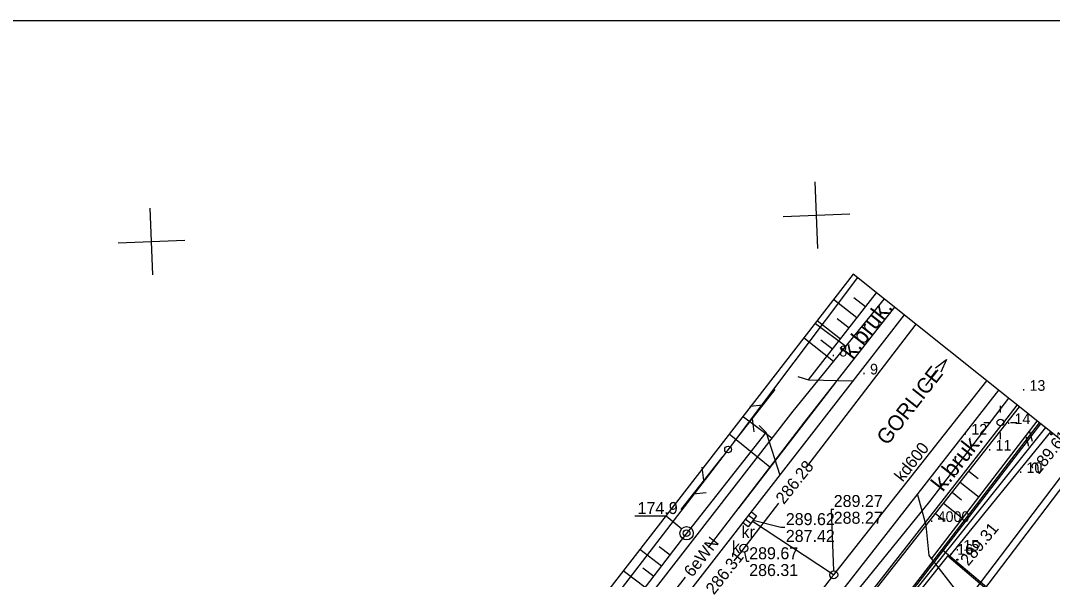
# Model space of a CAD drawing. Extents: x 4632591 to 4651936, y 5351032 to 5369988.
# Drawn here: x 4642040 to 4642117.6, y 5358443.5 to 5358485.5 of the extents above; entities that cross this region are included whole.
import ezdxf

# ---------------------------------------------------------------- set-up
doc = ezdxf.new("R2010")
doc.units = 0
for name, color, linetype in [('EBTOO_992', 7, 'Continuous'), ('EBUPP_312', 7, 'Continuous'), ('EDZPD_219', 7, 'Continuous'), ('EDZPX_299', 7, 'Continuous'), ('SDRPK_422', 7, 'Continuous'), ('SDRPK_423', 7, 'Continuous'), ('SDRPK_432', 7, 'Continuous'), ('SDRPZ_402', 7, 'Continuous'), ('SZOPO_902', 7, 'Continuous'), ('UEEPA_510', 7, 'Continuous'), ('UEEPB_665', 7, 'Continuous'), ('UEEPO_585', 7, 'Continuous'), ('UEETA_515', 7, 'Continuous'), ('UGGPO_583', 7, 'Continuous'), ('UKKPA_506', 7, 'Continuous'), ('UKKPA_509', 7, 'Continuous'), ('UKKPO_582', 7, 'Continuous'), ('UTTPA_510', 7, 'Continuous'), ('UTTPO_586', 7, 'Continuous'), ('UTTTA_521', 7, 'Continuous'), ('UWWPO_581', 7, 'Continuous'), ('Warstwa 40', 7, 'Continuous'), ('Warstwa 50', 7, 'Continuous'), ('Warstwa 62', 7, 'Continuous'), ('WUKPS_403', 7, 'Continuous'), ('WUKPS_820', 7, 'Continuous'), ('WUKPS_824', 7, 'Continuous')]:
    doc.layers.add(name, color=color, linetype=linetype)

msp = doc.modelspace()

# ---------------------------------------------------------------- linework, layer by layer
at = {"layer": 'EBTOO_992'}
for p, q in [((4642108.788, 5358459.423), (4642109.608, 5358460.048)), ((4642109.608, 5358460.048), (4642109.179, 5358459.111)), ((4642108.047, 5358458.095), (4642108.984, 5358459.267))]:
    msp.add_line(p, q, dxfattribs=at)
at = {"layer": 'EBUPP_312'}
msp.add_lwpolyline([(4642035.743, 5358485.503), (4642244.499, 5358485.503), (4642244.499, 5358312.184), (4642035.743, 5358312.184), (4642035.743, 5358485.503)], dxfattribs=at)
at = {"layer": 'EDZPD_219'}
for p, q in [((4642109.27, 5358445.775), (4642116.588, 5358455.295)), ((4642109.27, 5358445.775), (4642109.75, 5358445.38)), ((4642109.75, 5358445.38), (4642148.358, 5358413.139))]:
    msp.add_line(p, q, dxfattribs=at)
for points in [[(4642074.48, 5358401), (4642092.929, 5358424.649), (4642109.27, 5358445.775)], [(4642109.75, 5358445.38), (4642094.33, 5358426.05), (4642074.95, 5358400.6)]]:
    msp.add_lwpolyline(points, dxfattribs=at)
at = {"layer": 'EDZPX_299'}
for p, q in [((4642115.576, 5358454.275), (4642115.776, 5358453.553)), ((4642115.85, 5358454.632), (4642116.051, 5358453.909))]:
    msp.add_line(p, q, dxfattribs=at)
at = {"layer": 'SDRPK_422'}
for points in [[(4642046.346, 5358386.256), (4642059.209, 5358402.838), (4642079.221, 5358428.387), (4642102.017, 5358457.701), (4642106.446, 5358463.396)], [(4642113.514, 5358457.75), (4642105.042, 5358446.917), (4642085.281, 5358421.648), (4642072.27, 5358405.2)], [(4642100.957, 5358441.693), (4642104.539, 5358441.848), (4642104.903, 5358441.712), (4642105.55, 5358441.329), (4642105.987, 5358440.919), (4642106.147, 5358440.341), (4642106.12, 5358438.657), (4642088.824, 5358417.468), (4642123.987, 5358388.849), (4642145.015, 5358414.223), (4642111.485, 5358441.75), (4642110.376, 5358442.66), (4642108.299, 5358445.321), (4642108.074, 5358447.59), (4642107.425, 5358449.964)]]:
    msp.add_lwpolyline(points, dxfattribs=at)
at = {"layer": 'SDRPK_423'}
for p, q in [((4642099.249, 5358458.523), (4642104.354, 5358465.067)), ((4642096.05, 5358454.573), (4642095.54, 5358455.092)), ((4642096.05, 5358454.573), (4642097.095, 5358451.371))]:
    msp.add_line(p, q, dxfattribs=at)
for points in [[(4642098.43, 5358458.774), (4642099.249, 5358458.523), (4642102.593, 5358458.441)], [(4642072.479, 5358401.671), (4642079.888, 5358411.205), (4642089.716, 5358423.851), (4642098.108, 5358434.936), (4642107.953, 5358447.437), (4642113.681, 5358454.71), (4642115.09, 5358456.492)], [(4642069.391, 5358420.35), (4642082.068, 5358436.521), (4642089.705, 5358446.472), (4642096.05, 5358454.573)]]:
    msp.add_lwpolyline(points, dxfattribs=at)
at = {"layer": 'SDRPZ_402'}
msp.add_lwpolyline([(4642086.183, 5358448.308), (4642088.558, 5358448.308), (4642089.718, 5358447.344)], dxfattribs=at)
for radius in [0.5, 0.25]:
    msp.add_circle((4642090.084, 5358447.001), radius, dxfattribs=at)
at = {"layer": 'SZOPO_902'}
msp.add_lwpolyline([(4642148.207, 5358412.515), (4642109.784, 5358445.212), (4642117.44, 5358454.614)], dxfattribs=at)
at = {"layer": 'UEEPA_510'}
msp.add_circle((4642113.655, 5358455.327), 0.25, dxfattribs=at)
at = {"layer": 'UEEPB_665'}
msp.add_line((4642101.243, 5358458.292), (4642093.99, 5358448.878), dxfattribs=at)
at = {"layer": 'UEEPO_585'}
msp.add_line((4642096.345, 5358451.957), (4642093.282, 5358454.447), dxfattribs=at)
for points in [[(4642091.726, 5358445.94), (4642092.637, 5358447.108), (4642098.96, 5358455.378), (4642104.662, 5358462.655), (4642105.723, 5358463.973)], [(4642113.904, 5358455.322), (4642114.928, 5358456.621)], [(4642054.575, 5358379.16), (4642066.53, 5358394.148), (4642076.799, 5358407.337), (4642101.078, 5358438.902), (4642111.05, 5358451.701), (4642113.718, 5358455.085)], [(4642113.718, 5358455.085), (4642113.904, 5358455.322)], [(4642057.726, 5358402.161), (4642060.615, 5358405.826), (4642078.174, 5358428.552), (4642089.988, 5358443.709)]]:
    msp.add_lwpolyline(points, dxfattribs=at)
at = {"layer": 'UEETA_515'}
for p, q in [((4642113.655, 5358456.077), (4642113.655, 5358456.577)), ((4642112.405, 5358455.327), (4642112.905, 5358455.327)), ((4642114.405, 5358455.327), (4642114.905, 5358455.327)), ((4642113.655, 5358454.077), (4642113.655, 5358454.577))]:
    msp.add_line(p, q, dxfattribs=at)
at = {"layer": 'UGGPO_583'}
for p, q in [((4642102.042, 5358461.034), (4642099.763, 5358462.734)), ((4642101.117, 5358459.896), (4642098.928, 5358461.638)), ((4642094.361, 5358455.757), (4642096.522, 5358454.151))]:
    msp.add_line(p, q, dxfattribs=at)
for points in [[(4642075.495, 5358427.097), (4642090.53, 5358446.443), (4642098.099, 5358456.181), (4642104.938, 5358464.6)], [(4642116.682, 5358455.22), (4642109.134, 5358445.43), (4642104.05, 5358438.836), (4642089.709, 5358420.234), (4642080.639, 5358408.784), (4642072.095, 5358397.815), (4642060.525, 5358383.492), (4642056.06, 5358377.88)], [(4642117.035, 5358454.938), (4642102.445, 5358436.723), (4642096.695, 5358429.318), (4642094.232, 5358426.145), (4642093.25, 5358423.032), (4642091.283, 5358420.672), (4642088.305, 5358419.013), (4642086.886, 5358418.223), (4642082.568, 5358412.471), (4642075.744, 5358403.542), (4642069.267, 5358395.407)]]:
    msp.add_lwpolyline(points, dxfattribs=at)
at = {"layer": 'UKKPA_506'}
for points in [[(4642101.135, 5358448.794), (4642100.955, 5358448.794), (4642101.123, 5358444.178)], [(4642094.784, 5358444.87), (4642094.604, 5358444.87), (4642094.449, 5358445.582)]]:
    msp.add_lwpolyline(points, dxfattribs=at)
for centre in [(4642094.382, 5358445.874), (4642101.132, 5358443.878)]:
    msp.add_circle(centre, 0.3, dxfattribs=at)
at = {"layer": 'UKKPA_509'}
for p, q in [((4642094.519, 5358448.059), (4642094.914, 5358447.752)), ((4642095.129, 5358448.029), (4642094.734, 5358448.335))]:
    msp.add_line(p, q, dxfattribs=at)
msp.add_lwpolyline([(4642095.344, 5358448.305), (4642094.699, 5358447.476), (4642094.304, 5358447.783), (4642094.949, 5358448.612)], close=True, dxfattribs=at)
msp.add_lwpolyline([(4642097.474, 5358447.427), (4642097.172, 5358447.426), (4642095.071, 5358447.954)], dxfattribs=at)
at = {"layer": 'UKKPO_582'}
for p, q in [((4642101.318, 5358444.113), (4642112.639, 5358458.449)), ((4642095.034, 5358447.907), (4642100.882, 5358444.043)), ((4642095.034, 5358447.907), (4642095.034, 5358447.907)), ((4642100.882, 5358444.043), (4642101.132, 5358443.878)), ((4642101.132, 5358443.878), (4642101.318, 5358444.113))]:
    msp.add_line(p, q, dxfattribs=at)
for points in [[(4642107.313, 5358462.703), (4642099.089, 5358452)], [(4642096.993, 5358449.273), (4642094.564, 5358446.112)], [(4642094.195, 5358445.64), (4642093.631, 5358444.931)], [(4642094.564, 5358446.112), (4642094.382, 5358445.874), (4642094.195, 5358445.64)], [(4642100.948, 5358443.641), (4642083.594, 5358421.242)], [(4642101.132, 5358443.878), (4642100.948, 5358443.641)]]:
    msp.add_lwpolyline(points, dxfattribs=at)
at = {"layer": 'UTTPA_510'}
msp.add_circle((4642093.193, 5358453.292), 0.25, dxfattribs=at)
at = {"layer": 'UTTPO_586'}
for points in [[(4642102.924, 5358466.209), (4642093.343, 5358453.492)], [(4642095.93, 5358433.734), (4642101.678, 5358441.143), (4642108.351, 5358449.397), (4642114.279, 5358457.139)], [(4642093.343, 5358453.492), (4642093.097, 5358453.165), (4642093.042, 5358453.093)], [(4642093.343, 5358453.492), (4642093.097, 5358453.165)], [(4642093.042, 5358453.093), (4642082.847, 5358439.786), (4642080.261, 5358436.411)], [(4642093.097, 5358453.165), (4642093.042, 5358453.093)]]:
    msp.add_lwpolyline(points, dxfattribs=at)
at = {"layer": 'UTTTA_521'}
for p, q in [((4642093.652, 5358453.879), (4642096.744, 5358457.808)), ((4642095.816, 5358456.629), (4642094.824, 5358456.511)), ((4642095.017, 5358455.613), (4642095.135, 5358454.62)), ((4642092.733, 5358452.701), (4642089.638, 5358448.774)), ((4642091.367, 5358450.967), (4642091.249, 5358451.96)), ((4642090.566, 5358449.952), (4642091.559, 5358450.069))]:
    msp.add_line(p, q, dxfattribs=at)
at = {"layer": 'UWWPO_581'}
for points in [[(4642119.505, 5358452.965), (4642092.32, 5358417.221), (4642069.914, 5358387.761), (4642059.891, 5358374.577)], [(4642119.925, 5358452.629), (4642092.728, 5358416.87), (4642070.321, 5358387.409), (4642060.298, 5358374.225)]]:
    msp.add_lwpolyline(points, dxfattribs=at)
at = {"layer": 'Warstwa 40'}
for p, q in [((4642102.603, 5358466.465), (4642042.779, 5358389.332)), ((4642171.648, 5358411.317), (4642102.603, 5358466.465))]:
    msp.add_line(p, q, dxfattribs=at)
at = {"layer": 'Warstwa 50'}
for p, q in [((4642099.944, 5358468.395), (4642099.746, 5358473.391)), ((4642049.983, 5358466.417), (4642049.785, 5358471.413)), ((4642097.347, 5358470.794), (4642102.343, 5358470.992)), ((4642047.386, 5358468.816), (4642052.382, 5358469.013))]:
    msp.add_line(p, q, dxfattribs=at)
at = {"layer": 'WUKPS_403'}
for centre in [(4642117.484, 5358454.437), (4642110.418, 5358445.019)]:
    msp.add_circle(centre, 0.045, dxfattribs=at)
at = {"layer": 'WUKPS_820'}
for p, q in [((4642102.882, 5358463.18), (4642101.121, 5358464.554)), ((4642103.526, 5358464.006), (4642102.644, 5358464.693)), ((4642101.641, 5358461.589), (4642099.884, 5358462.959)), ((4642102.284, 5358462.414), (4642101.405, 5358463.1)), ((4642101.043, 5358460.822), (4642100.166, 5358461.506)), ((4642111.279, 5358451.66), (4642111.983, 5358451.105)), ((4642110.633, 5358450.839), (4642112.052, 5358449.72)), ((4642110.032, 5358450.076), (4642110.747, 5358449.513)), ((4642109.385, 5358449.255), (4642110.826, 5358448.12)), ((4642108.785, 5358448.492), (4642109.51, 5358447.921)), ((4642088.205, 5358444.518), (4642086.561, 5358445.78)), ((4642088.841, 5358445.347), (4642088.021, 5358445.976)), ((4642086.977, 5358442.918), (4642085.325, 5358444.187)), ((4642087.614, 5358443.748), (4642086.79, 5358444.38))]:
    msp.add_line(p, q, dxfattribs=at)
at = {"layer": 'WUKPS_824'}
msp.add_line((4642108.492, 5358445.073), (4642116.423, 5358455.427), dxfattribs=at)

# ---------------------------------------------------------------- texts
at = {"layer": 'SDRPK_423'}
for rotation, p in [(52.04581, (4642102.543, 5358460.005)), (51.77673, (4642109.331, 5358450.059))]:
    msp.add_text('k.bruk.', height=1.25, rotation=rotation, dxfattribs=at).set_placement(p)
at = {"layer": 'SDRPK_432'}
msp.add_text('GORLICE', height=1.1459, rotation=51.97327, dxfattribs=at).set_placement((4642105.16, 5358453.54))
at = {"layer": 'SDRPZ_402'}
msp.add_text('174.9', height=0.9, dxfattribs=at).set_placement((4642086.399, 5358448.445))
at = {"layer": 'UEEPO_585'}
msp.add_text('6eWN', height=0.9, rotation=52.06726, dxfattribs=at).set_placement((4642090.509, 5358443.647))
at = {"layer": 'UKKPA_506'}
for s, p in [('289.27', (4642101.135, 5358448.974)), ('288.27', (4642101.135, 5358447.714)), ('kr', (4642094.204, 5358446.653)), ('k', (4642093.484, 5358445.516)), ('289.67', (4642094.784, 5358445.049)), ('286.31', (4642094.784, 5358443.789))]:
    msp.add_text(s, height=0.9, dxfattribs=at).set_placement(p)
at = {"layer": 'UKKPA_509'}
for s, p in [('289.62', (4642097.535, 5358447.613)), ('287.42', (4642097.535, 5358446.353))]:
    msp.add_text(s, height=0.9, dxfattribs=at).set_placement(p)
at = {"layer": 'UKKPO_582'}
for s, rotation, p in [('kd600', 51.70395, (4642106.318, 5358450.808)), ('286.28', 51.50473, (4642097.394, 5358449.123)), ('286.31', 51.50473, (4642092.138, 5358442.33))]:
    msp.add_text(s, height=0.9, rotation=rotation, dxfattribs=at).set_placement(p)
at = {"layer": 'Warstwa 62'}
for s, p in [('. 8', (4642100.96, 5358460.28)), ('. 9', (4642103.27, 5358458.93)), ('. 13', (4642115.25, 5358457.7)), ('. 14', (4642114.12, 5358455.2)), ('. 12', (4642110.88, 5358454.41)), ('. 11', (4642112.7, 5358453.21)), ('. 10', (4642115.02, 5358451.53)), ('. 4000', (4642108.35, 5358447.85)), ('. 4000', (4642108.35, 5358447.85)), ('. 15', (4642110.28, 5358445.69)), ('. 16', (4642109.82, 5358445.39))]:
    msp.add_text(s, height=0.8, dxfattribs=at).set_placement(p)
at = {"layer": 'WUKPS_403'}
for s, rotation, p in [('289.61', 50.98076, (4642116.547, 5358451.382)), ('289.31', 50.5815, (4642111.247, 5358444.492))]:
    msp.add_text(s, height=0.9, rotation=rotation, dxfattribs=at).set_placement(p)

doc.saveas('drawing.dxf')
